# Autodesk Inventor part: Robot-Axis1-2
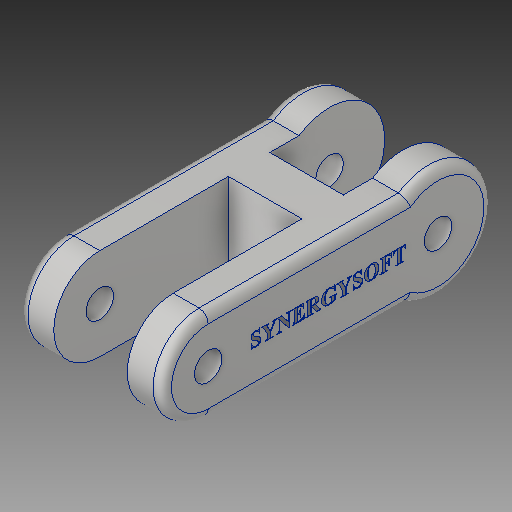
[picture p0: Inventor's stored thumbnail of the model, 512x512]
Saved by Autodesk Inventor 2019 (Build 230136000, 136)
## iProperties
Created: 2018-07
Part Number: Robot-Axis1-2
Material: Aluminum 6061
Description: 123456
Document SubType Name: Modeling
Designer: Power User
Mass: 7772.34 g
Surface Area: 2206.67 cm^2
Volume: 2878.64 cm^3
Density: 2.7 g/cm^3
Appearance: Aluminum - Flat
Title: GEAR
Author: Power User
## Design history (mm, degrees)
sketch "Sketch6"
  geometry: L1 (0, 250)-(0, 0); L2 (-50, 250)-(-50, 0); L3 (50, 0)-(50, 250); C1 r 15 at (0, 0); C2 r 60 at (0, 0); C3 r 15 at (0, 250); A1 r 50 centre (0, 250) between (50, 250) and (-50, 250); A2 r 50 centre (0, 0) between (-50, 0) and (50, 0); 2 further points
  constraints: 8 end point, 5 centre point, 4 point on circle, 4 tangent, 3 coincident, 1 midpoint, 1 parallel, 1 vertical
  dimensions: "d44" = 30 diameter of C1; "d45" = 120 diameter of C2; "d46" = 100 diameter of A2; "d47" = 250 distance of L1.start L1.end; "d48" = 30 diameter of C3
extrude "Extrusion5" new body sketch "Sketch6" stored distance "d49" = 156; taper "d50" = 0 deg
sketch "Sketch7"
  geometry: L1 (40, 300)-(-40, 300); L2 (-40, 300)-(-40, 110); L3 (-40, 110)-(40, 110); L4 (40, 110)-(40, 300); L5 (40, 65)-(-40, 65); L6 (-40, 65)-(-40, -60); L7 (-40, -60)-(40, -60); L8 (40, -60)-(40, 65); L9 (78, 265)-(-78, 265) reference; L10 (-78, 265)-(-78, 300) reference; L11 (-78, 300)-(78, 300) reference; L12 (78, 300)-(78, 265) reference; L13 (-78, -15)-(78, -15) reference; L14 (78, -15)-(78, -60) reference; L15 (78, -60)-(-78, -60) reference; L16 (-78, -60)-(-78, -15) reference; L17 (78, 15)-(-78, 15) reference; L18 (-78, 15)-(-78, 235) reference; L19 (-78, 235)-(78, 235) reference; L20 (78, 235)-(78, 15) reference; 2 further points
  constraints: 16 end point, 4 collinear, 4 parallel, 2 horizontal, 2 perpendicular, 1 midpoint, 1 vertical alignment
  dimensions: "d51" = 45 distance between parallel lines of L5 L3; "d52" = 125 distance of L5.end L6.end; "d53" = 80 distance of L1.start L1.end
extrude "Extrusion6" cut sketch "Sketch7" extent not by distance; stored distance "d54" = 156; taper "d55" = 0 deg
fillet "Fillet2" dims "d56" = 10
sketch "Sketch8"
  geometry: L1 (-208.793, 20.97)-(-30, 20.97); L2 (-30, 20.97)-(-30, -20.97); L3 (-30, -20.97)-(-208.793, -20.97); L4 (-208.793, -20.97)-(-208.793, 20.97); 2 further points
  constraints: 1 horizontal, 1 horizontal alignment, 1 midpoint, 2 other
  dimensions: "d57" = 30 distance from line of point (0, 0) L2
emboss "Emboss1" sketch "Sketch8" dims "d44" = 30, "d45" = 120, "d46" = 100, "d47" = 250, "d48" = 30, "d58" = 0.5, "d59" = 0
body "Solid2"
node "Project Cut Edges2"
